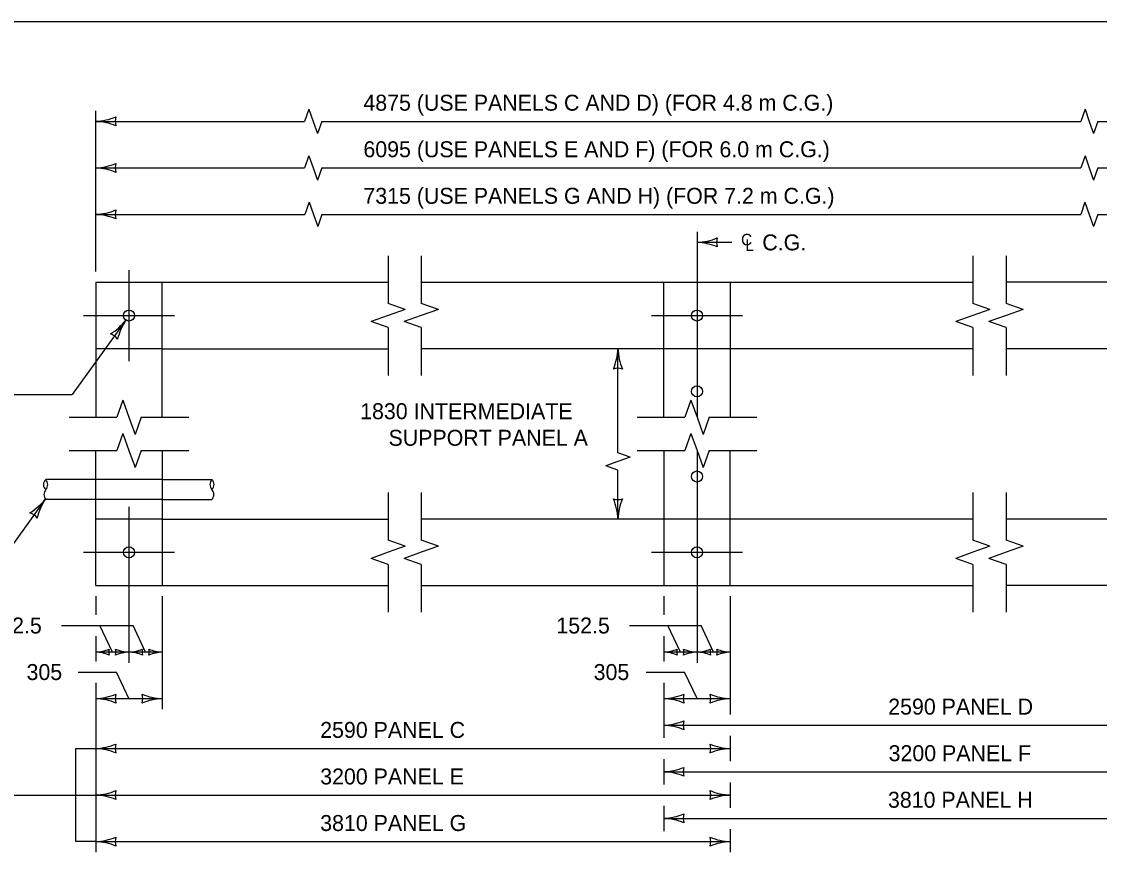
# Model space of a CAD drawing. Extents: x 49991.4 to 50021, y 49987.6 to 50011.4.
# Drawn here: x 50001.425 to 50005.475, y 49995.82 to 49998.999 of the extents above; entities that cross this region are included whole.
import ezdxf

# ---------------------------------------------------------------- set-up
doc = ezdxf.new("R2010")
doc.units = 0
for name, color, linetype in [('Level 1', 7, 'Continuous'), ('Level 10', 7, 'Continuous'), ('Level 2', 7, 'Continuous'), ('Level 3', 7, 'Continuous'), ('Level 4', 7, 'Continuous'), ('Level 5', 7, 'Continuous'), ('Level 6', 7, 'Continuous')]:
    doc.layers.add(name, color=color, linetype=linetype)

msp = doc.modelspace()

# ---------------------------------------------------------------- linework, layer by layer
at = {"layer": 'Level 1'}
for p, q in [((50001.7038, 49998.0191), (50002.8021, 49998.0191)), ((50001.7038, 49998.0191), (50001.7038, 49997.5116)), ((50001.9538, 49997.5116), (50001.9538, 49998.0191)), ((50002.9271, 49998.0191), (50004.9986, 49998.0191)), ((50003.8378, 49997.5116), (50003.8378, 49998.0191)), ((50006.2218, 49998.0191), (50005.1236, 49998.0191)), ((50001.9538, 49997.7691), (50002.8021, 49997.7691)), ((50004.9986, 49997.7691), (50002.9271, 49997.7691)), ((50004.0878, 49997.7691), (50004.0878, 49997.5116)), ((50005.9718, 49997.7691), (50005.1236, 49997.7691)), ((50001.7038, 49996.8791), (50001.7038, 49997.3866)), ((50001.9538, 49997.3866), (50001.9538, 49996.8791)), ((50003.8378, 49997.3866), (50003.8378, 49996.8791)), ((50004.0878, 49997.1291), (50004.0878, 49997.3866)), ((50001.7038, 49997.2775), (50001.5163, 49997.2775)), ((50001.9538, 49997.2775), (50002.1406, 49997.2775)), ((50001.7038, 49997.2025), (50001.5165, 49997.2025)), ((50001.9538, 49997.2025), (50002.1404, 49997.2025)), ((50001.9538, 49997.1291), (50002.8021, 49997.1291)), ((50004.9986, 49997.1291), (50002.9271, 49997.1291)), ((50005.9718, 49997.1291), (50005.1236, 49997.1291)), ((50001.7038, 49996.8791), (50002.8021, 49996.8791)), ((50002.9271, 49996.8791), (50004.9986, 49996.8791)), ((50006.2218, 49996.8791), (50005.1236, 49996.8791))]:
    msp.add_line(p, q, dxfattribs=at)
msp.add_lwpolyline([(49999.3835, 49998.9992), (50016.7501, 49998.9992), (50016.7501, 49987.7988), (49999.3835, 49987.7988)], close=True, dxfattribs=at)
for centre in [(50001.8287, 49997.8941), (50003.9627, 49997.8941), (50003.9627, 49997.6091), (50003.9627, 49997.2891), (50001.8287, 49997.0041), (50003.9627, 49997.0041)]:
    msp.add_circle(centre, 0.0208, dxfattribs=at)
for centre, radius, start, end in [((50001.5315, 49997.2589), 0.0241, 129.2484, 231.5424), ((50001.4959, 49997.2586), 0.0278, 317.969, 42.8218), ((50002.1604, 49997.2586), 0.0273, 136.3219, 222.8873), ((50002.1226, 49997.2589), 0.0259, 313.3067, 45.9026), ((50001.5375, 49997.2212), 0.0281, 138.1897, 221.8103), ((50002.1194, 49997.2212), 0.0281, 318.1897, 41.8103)]:
    msp.add_arc(centre, radius, start, end, dxfattribs=at)
at = {"layer": 'Level 3'}
for p, q in [((50001.7038, 49998.0591), (50001.7038, 49998.6641)), ((50002.505, 49998.6698), (50002.4888, 49998.6241)), ((50002.505, 49998.6698), (50002.5212, 49998.6241)), ((50005.4204, 49998.6698), (50005.4042, 49998.6241)), ((50005.4204, 49998.6698), (50005.4366, 49998.6241)), ((50001.7038, 49998.6241), (50002.4888, 49998.6241)), ((50002.5212, 49998.6241), (50002.5374, 49998.5784)), ((50002.5536, 49998.6241), (50002.5374, 49998.5784)), ((50002.5536, 49998.6241), (50005.4042, 49998.6241)), ((50005.4366, 49998.6241), (50005.4528, 49998.5784)), ((50005.469, 49998.6241), (50005.4528, 49998.5784)), ((50005.469, 49998.6241), (50006.2218, 49998.6241)), ((50002.5048, 49998.4948), (50002.4886, 49998.4491)), ((50002.5048, 49998.4948), (50002.521, 49998.4491)), ((50005.4204, 49998.4948), (50005.4042, 49998.4491)), ((50005.4204, 49998.4948), (50005.4366, 49998.4491)), ((50001.7038, 49998.4491), (50002.4886, 49998.4491)), ((50002.521, 49998.4491), (50002.5372, 49998.4034)), ((50002.5534, 49998.4491), (50002.5372, 49998.4034)), ((50002.5534, 49998.4491), (50005.4042, 49998.4491)), ((50005.4366, 49998.4491), (50005.4528, 49998.4034)), ((50005.469, 49998.4491), (50005.4528, 49998.4034)), ((50005.469, 49998.4491), (50006.2218, 49998.4491)), ((50002.5053, 49998.3198), (50002.4891, 49998.2741)), ((50002.5053, 49998.3198), (50002.5215, 49998.2741)), ((50005.4203, 49998.3198), (50005.4041, 49998.2741)), ((50005.4203, 49998.3198), (50005.4365, 49998.2741)), ((50001.7038, 49998.2741), (50002.4891, 49998.2741)), ((50002.5215, 49998.2741), (50002.5377, 49998.2284)), ((50002.5539, 49998.2741), (50002.5377, 49998.2284)), ((50002.5539, 49998.2741), (50005.4041, 49998.2741)), ((50005.4365, 49998.2741), (50005.4527, 49998.2284)), ((50005.4689, 49998.2741), (50005.4527, 49998.2284)), ((50005.4689, 49998.2741), (50006.2218, 49998.2741)), ((50004.0938, 49998.1691), (50003.9628, 49998.1691)), ((50001.817, 49997.8768), (50001.6157, 49997.5969)), ((50003.6656, 49997.3782), (50003.6656, 49997.7691)), ((50000.7897, 49997.5969), (50001.6157, 49997.5969)), ((50003.6656, 49997.3458), (50003.6199, 49997.3296)), ((50003.7113, 49997.362), (50003.6656, 49997.3782)), ((50003.7113, 49997.362), (50003.6656, 49997.3458)), ((50003.6656, 49997.3134), (50003.6199, 49997.3296)), ((50003.6656, 49997.1291), (50003.6656, 49997.3134)), ((50001.5149, 49997.2046), (50001.3035, 49996.9108)), ((50001.7038, 49996.8391), (50001.7038, 49996.7691)), ((50001.9538, 49996.8391), (50001.9538, 49996.4141)), ((50003.8378, 49996.8391), (50003.8378, 49996.7691)), ((50004.0878, 49996.8391), (50004.0878, 49996.3941)), ((50001.5755, 49996.7291), (50001.8445, 49996.7291)), ((50001.7663, 49996.6291), (50001.7195, 49996.7291)), ((50001.8913, 49996.6291), (50001.8445, 49996.7291)), ((50003.7095, 49996.7291), (50003.9785, 49996.7291)), ((50003.9003, 49996.6291), (50003.8535, 49996.7291)), ((50004.0253, 49996.6291), (50003.9785, 49996.7291)), ((50001.7038, 49996.6891), (50001.7038, 49996.5941)), ((50003.8378, 49996.6891), (50003.8378, 49996.5941)), ((50001.8288, 49996.6291), (50001.7038, 49996.6291)), ((50001.9538, 49996.6291), (50001.8288, 49996.6291)), ((50003.9628, 49996.6291), (50003.8378, 49996.6291)), ((50004.0878, 49996.6291), (50003.9628, 49996.6291)), ((50001.638, 49996.5541), (50001.782, 49996.5541)), ((50001.8288, 49996.4541), (50001.782, 49996.5541)), ((50003.772, 49996.5541), (50003.916, 49996.5541)), ((50003.9628, 49996.4541), (50003.916, 49996.5541)), ((50001.7038, 49996.5141), (50001.7038, 49995.8766)), ((50003.8378, 49996.5141), (50003.8378, 49996.3066)), ((50001.7038, 49996.4541), (50001.9538, 49996.4541)), ((50003.8378, 49996.4541), (50004.0878, 49996.4541)), ((50003.8378, 49996.3541), (50006.2218, 49996.3541)), ((50004.0878, 49996.3141), (50004.0878, 49996.2191)), ((50001.6288, 49995.9166), (50001.6288, 49996.2666)), ((50001.6288, 49996.2666), (50001.7038, 49996.2666)), ((50001.7038, 49996.2666), (50004.0878, 49996.2666)), ((50003.8378, 49996.2266), (50003.8378, 49996.1316)), ((50003.8378, 49996.1791), (50006.2218, 49996.1791)), ((50004.0878, 49996.1391), (50004.0878, 49996.0441)), ((50000.8395, 49996.0916), (50001.7038, 49996.0916)), ((50001.7038, 49996.0916), (50004.0878, 49996.0916)), ((50003.8378, 49996.0516), (50003.8378, 49995.9566)), ((50003.8378, 49996.0041), (50006.2218, 49996.0041)), ((50004.0878, 49995.9641), (50004.0878, 49995.8766)), ((50001.7038, 49995.9166), (50001.6288, 49995.9166)), ((50001.7038, 49995.9166), (50004.0878, 49995.9166))]:
    msp.add_line(p, q, dxfattribs=at)
for centre, radius, start, end in [((50001.6923, 49998.8568), 0.233, 272.8273, 292.0772), ((50001.832, 49998.6241), 0.0548, 162.1388, 197.8612), ((50001.6946, 49998.402), 0.2223, 67.456, 87.6395), ((50001.6923, 49998.6818), 0.233, 272.8273, 292.0772), ((50001.6946, 49998.227), 0.2223, 67.456, 87.6395), ((50001.832, 49998.4491), 0.0548, 162.1388, 197.8612), ((50001.6923, 49998.5068), 0.233, 272.8273, 292.0772), ((50001.6946, 49998.052), 0.2223, 67.456, 87.6395), ((50001.832, 49998.2741), 0.0548, 162.1388, 197.8612), ((50003.9513, 49998.4018), 0.233, 272.8273, 292.0772), ((50003.9536, 49997.947), 0.2223, 67.456, 87.6395), ((50004.091, 49998.1691), 0.0548, 162.1388, 197.8612), ((50001.6421, 49998.014), 0.2223, 301.7291, 321.9126), ((50002.0127, 49997.7503), 0.233, 147.1004, 166.3502), ((50001.7422, 49997.7727), 0.0548, 36.4119, 72.1343), ((50003.4435, 49997.7783), 0.2223, 337.456, 357.6395), ((50003.8983, 49997.7806), 0.233, 182.8273, 202.0772), ((50003.6656, 49997.6409), 0.0548, 72.1388, 107.8612), ((50001.3399, 49997.3417), 0.2223, 301.7291, 321.9126), ((50001.7105, 49997.078), 0.233, 147.1004, 166.3502), ((50003.6656, 49997.2573), 0.0548, 252.1388, 287.8612), ((50003.4329, 49997.1176), 0.233, 2.8273, 22.0772), ((50003.8877, 49997.1199), 0.2223, 157.456, 177.6395), ((50001.44, 49997.1005), 0.0548, 36.4119, 72.1343), ((50001.6961, 49996.7842), 0.1553, 272.8273, 292.0772), ((50001.6977, 49996.481), 0.1482, 67.456, 87.6395), ((50001.7893, 49996.6291), 0.0365, 162.1388, 197.8612), ((50001.8349, 49996.7772), 0.1482, 247.456, 267.6395), ((50001.7433, 49996.6291), 0.0365, 342.1388, 17.8612), ((50001.8365, 49996.474), 0.1553, 92.8273, 112.0772), ((50001.8211, 49996.7842), 0.1553, 272.8273, 292.0772), ((50001.8227, 49996.481), 0.1482, 67.456, 87.6395), ((50001.9143, 49996.6291), 0.0365, 162.1388, 197.8612), ((50001.9599, 49996.7772), 0.1482, 247.456, 267.6395), ((50001.8683, 49996.6291), 0.0365, 342.1388, 17.8612), ((50001.9615, 49996.474), 0.1553, 92.8273, 112.0772), ((50003.8301, 49996.7842), 0.1553, 272.8273, 292.0772), ((50003.8317, 49996.481), 0.1482, 67.456, 87.6395), ((50003.9233, 49996.6291), 0.0365, 162.1388, 197.8612), ((50003.9689, 49996.7772), 0.1482, 247.456, 267.6395), ((50003.8773, 49996.6291), 0.0365, 342.1388, 17.8612), ((50003.9705, 49996.474), 0.1553, 92.8273, 112.0772), ((50003.9551, 49996.7842), 0.1553, 272.8273, 292.0772), ((50003.9567, 49996.481), 0.1482, 67.456, 87.6395), ((50004.0483, 49996.6291), 0.0365, 162.1388, 197.8612), ((50004.0939, 49996.7772), 0.1482, 247.456, 267.6395), ((50004.0023, 49996.6291), 0.0365, 342.1388, 17.8612), ((50004.0955, 49996.474), 0.1553, 92.8273, 112.0772), ((50001.6923, 49996.6868), 0.233, 272.8273, 292.0772), ((50001.6946, 49996.232), 0.2223, 67.456, 87.6395), ((50001.832, 49996.4541), 0.0548, 162.1388, 197.8612), ((50001.963, 49996.6762), 0.2223, 247.456, 267.6395), ((50001.8256, 49996.4541), 0.0548, 342.1388, 17.8612), ((50001.9653, 49996.2214), 0.233, 92.8273, 112.0772), ((50003.8263, 49996.6868), 0.233, 272.8273, 292.0772), ((50003.8286, 49996.232), 0.2223, 67.456, 87.6395), ((50003.966, 49996.4541), 0.0548, 162.1388, 197.8612), ((50004.097, 49996.6762), 0.2223, 247.456, 267.6395), ((50003.9596, 49996.4541), 0.0548, 342.1388, 17.8612), ((50004.0993, 49996.2214), 0.233, 92.8273, 112.0772), ((50003.8263, 49996.5868), 0.233, 272.8273, 292.0772), ((50003.966, 49996.3541), 0.0548, 162.1388, 197.8612), ((50003.8286, 49996.132), 0.2223, 67.456, 87.6395), ((50001.6923, 49996.4993), 0.233, 272.8273, 292.0772), ((50001.6946, 49996.0445), 0.2223, 67.456, 87.6395), ((50001.832, 49996.2666), 0.0548, 162.1388, 197.8612), ((50004.097, 49996.4887), 0.2223, 247.456, 267.6395), ((50003.9596, 49996.2666), 0.0548, 342.1388, 17.8612), ((50004.0993, 49996.0339), 0.233, 92.8273, 112.0772), ((50003.8263, 49996.4118), 0.233, 272.8273, 292.0772), ((50003.8286, 49995.957), 0.2223, 67.456, 87.6395), ((50003.966, 49996.1791), 0.0548, 162.1388, 197.8612), ((50001.6923, 49996.3243), 0.233, 272.8273, 292.0772), ((50001.6946, 49995.8695), 0.2223, 67.456, 87.6395), ((50001.832, 49996.0916), 0.0548, 162.1388, 197.8612), ((50004.097, 49996.3137), 0.2223, 247.456, 267.6395), ((50003.9596, 49996.0916), 0.0548, 342.1388, 17.8612), ((50004.0993, 49995.8589), 0.233, 92.8273, 112.0772), ((50003.8263, 49996.2368), 0.233, 272.8273, 292.0772), ((50003.8286, 49995.782), 0.2223, 67.456, 87.6395), ((50003.966, 49996.0041), 0.0548, 162.1388, 197.8612), ((50001.6923, 49996.1493), 0.233, 272.8273, 292.0772), ((50001.832, 49995.9166), 0.0548, 162.1388, 197.8612), ((50004.097, 49996.1387), 0.2223, 247.456, 267.6395), ((50003.9596, 49995.9166), 0.0548, 342.1388, 17.8612), ((50001.6946, 49995.6945), 0.2223, 67.456, 87.6395), ((50004.0993, 49995.6839), 0.233, 92.8273, 112.0772)]:
    msp.add_arc(centre, radius, start, end, dxfattribs=at)
at = {"layer": 'Level 4'}
for p, q in [((50004.0878, 49998.0191), (50004.0878, 49997.7691)), ((50001.9538, 49997.7691), (50001.7038, 49997.7691)), ((50001.9538, 49997.2775), (50001.7038, 49997.2775)), ((50001.9538, 49997.2025), (50001.7038, 49997.2025)), ((50001.9538, 49997.1291), (50001.7038, 49997.1291)), ((50004.0878, 49996.8791), (50004.0878, 49997.1291))]:
    msp.add_line(p, q, dxfattribs=at)
at = {"layer": 'Level 5'}
for p, q in [((50003.9628, 49998.2091), (50003.9628, 49997.5116)), ((50001.8288, 49998.0649), (50001.8288, 49997.7232)), ((50001.6579, 49997.8941), (50001.9996, 49997.8941)), ((50003.7919, 49997.8941), (50004.1336, 49997.8941)), ((50003.9628, 49997.3866), (50003.9628, 49996.5891)), ((50001.8288, 49997.1749), (50001.8288, 49996.5891)), ((50001.6579, 49997.0041), (50001.9996, 49997.0041)), ((50003.7919, 49997.0041), (50004.1336, 49997.0041))]:
    msp.add_line(p, q, dxfattribs=at)
at = {"layer": 'Level 6'}
for p, q in [((50002.8021, 49998.1191), (50002.8021, 49997.9395)), ((50002.9271, 49998.1191), (50002.9271, 49997.9395)), ((50004.9986, 49998.1191), (50004.9986, 49997.9395)), ((50005.1236, 49998.1191), (50005.1236, 49997.9395)), ((50002.8661, 49997.9168), (50002.8021, 49997.9395)), ((50002.8661, 49997.9168), (50002.8021, 49997.8941)), ((50002.9911, 49997.9168), (50002.9271, 49997.9395)), ((50002.9911, 49997.9168), (50002.9271, 49997.8941)), ((50005.0626, 49997.9168), (50004.9986, 49997.9395)), ((50005.0626, 49997.9168), (50004.9986, 49997.8941)), ((50005.1876, 49997.9168), (50005.1236, 49997.9395)), ((50005.1876, 49997.9168), (50005.1236, 49997.8941)), ((50002.8021, 49997.8941), (50002.7381, 49997.8714)), ((50002.8021, 49997.8487), (50002.7381, 49997.8714)), ((50002.9271, 49997.8941), (50002.8631, 49997.8714)), ((50002.9271, 49997.8487), (50002.8631, 49997.8714)), ((50004.9986, 49997.8941), (50004.9346, 49997.8714)), ((50004.9986, 49997.8487), (50004.9346, 49997.8714)), ((50005.1236, 49997.8941), (50005.0596, 49997.8714)), ((50005.1236, 49997.8487), (50005.0596, 49997.8714)), ((50002.8021, 49997.8487), (50002.8021, 49997.6691)), ((50002.9271, 49997.8487), (50002.9271, 49997.6691)), ((50004.9986, 49997.8487), (50004.9986, 49997.6691)), ((50005.1236, 49997.8487), (50005.1236, 49997.6691)), ((50001.8061, 49997.5756), (50001.7834, 49997.5116)), ((50001.8061, 49997.5756), (50001.8288, 49997.5116)), ((50003.9401, 49997.5756), (50003.9174, 49997.5116)), ((50003.9401, 49997.5756), (50003.9628, 49997.5116)), ((50001.6038, 49997.5116), (50001.7834, 49997.5116)), ((50001.8288, 49997.5116), (50001.8515, 49997.4476)), ((50001.8742, 49997.5116), (50001.8515, 49997.4476)), ((50001.8742, 49997.5116), (50002.0538, 49997.5116)), ((50003.7378, 49997.5116), (50003.9174, 49997.5116)), ((50003.9628, 49997.5116), (50003.9855, 49997.4476)), ((50004.0082, 49997.5116), (50003.9855, 49997.4476)), ((50004.0082, 49997.5116), (50004.1878, 49997.5116)), ((50001.8061, 49997.4506), (50001.7834, 49997.3866)), ((50001.8061, 49997.4506), (50001.8288, 49997.3866)), ((50003.9401, 49997.4506), (50003.9174, 49997.3866)), ((50003.9401, 49997.4506), (50003.9628, 49997.3866)), ((50001.6038, 49997.3866), (50001.7834, 49997.3866)), ((50001.8288, 49997.3866), (50001.8515, 49997.3226)), ((50001.8742, 49997.3866), (50001.8515, 49997.3226)), ((50001.8742, 49997.3866), (50002.0538, 49997.3866)), ((50003.7378, 49997.3866), (50003.9174, 49997.3866)), ((50003.9628, 49997.3866), (50003.9855, 49997.3226)), ((50004.0082, 49997.3866), (50003.9855, 49997.3226)), ((50004.0082, 49997.3866), (50004.1878, 49997.3866)), ((50002.8021, 49997.2291), (50002.8021, 49997.0495)), ((50002.9271, 49997.2291), (50002.9271, 49997.0495)), ((50004.9986, 49997.2291), (50004.9986, 49997.0495)), ((50005.1236, 49997.2291), (50005.1236, 49997.0495)), ((50002.8661, 49997.0268), (50002.8021, 49997.0495)), ((50002.8661, 49997.0268), (50002.8021, 49997.0041)), ((50002.9911, 49997.0268), (50002.9271, 49997.0495)), ((50002.9911, 49997.0268), (50002.9271, 49997.0041)), ((50005.0626, 49997.0268), (50004.9986, 49997.0495)), ((50005.0626, 49997.0268), (50004.9986, 49997.0041)), ((50005.1876, 49997.0268), (50005.1236, 49997.0495)), ((50005.1876, 49997.0268), (50005.1236, 49997.0041)), ((50002.8021, 49997.0041), (50002.7381, 49996.9814)), ((50002.8021, 49996.9587), (50002.7381, 49996.9814)), ((50002.9271, 49997.0041), (50002.8631, 49996.9814)), ((50002.9271, 49996.9587), (50002.8631, 49996.9814)), ((50004.9986, 49997.0041), (50004.9346, 49996.9814)), ((50004.9986, 49996.9587), (50004.9346, 49996.9814)), ((50005.1236, 49997.0041), (50005.0596, 49996.9814)), ((50005.1236, 49996.9587), (50005.0596, 49996.9814)), ((50002.8021, 49996.9587), (50002.8021, 49996.7791)), ((50002.9271, 49996.9587), (50002.9271, 49996.7791)), ((50004.9986, 49996.9587), (50004.9986, 49996.7791)), ((50005.1236, 49996.9587), (50005.1236, 49996.7791))]:
    msp.add_line(p, q, dxfattribs=at)

# ---------------------------------------------------------------- texts
at = {"layer": 'Level 10'}
for s, p in [('C', (50004.1282, 49998.158)), ('L', (50004.1446, 49998.1368))]:
    msp.add_text(s, height=0.0432, dxfattribs=at).set_placement(p)
at = {"layer": 'Level 2'}
for s, p in [('4875 (USE PANELS C AND D) (FOR 4.8 m C.G.)', (50002.7094, 49998.6641)), ('6095 (USE PANELS E AND F) (FOR 6.0 m C.G.)', (50002.7095, 49998.4891)), ('7315 (USE PANELS G AND H) (FOR 7.2 m C.G.)', (50002.7094, 49998.3141)), ('C.G.', (50004.2081, 49998.1391)), ('1830 INTERMEDIATE', (50002.6973, 49997.5046)), ('SUPPORT PANEL A', (50002.8039, 49997.4046)), ('152.5', (50001.3004, 49996.6991)), ('152.5', (50003.4344, 49996.6991)), ('305', (50001.444, 49996.5241)), ('305', (50003.5744, 49996.5241)), ('2590 PANEL D', (50004.6812, 49996.3941)), ('2590 PANEL C', (50002.5472, 49996.3066)), ('3200 PANEL F', (50004.6826, 49996.2191)), ('3200 PANEL E', (50002.5472, 49996.1316)), ('3810 PANEL H', (50004.6802, 49996.0441)), ('3810 PANEL G', (50002.5472, 49995.9566))]:
    msp.add_text(s, height=0.06, dxfattribs=at).set_placement(p)

doc.saveas('drawing.dxf')
